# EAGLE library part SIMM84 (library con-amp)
AMP connector
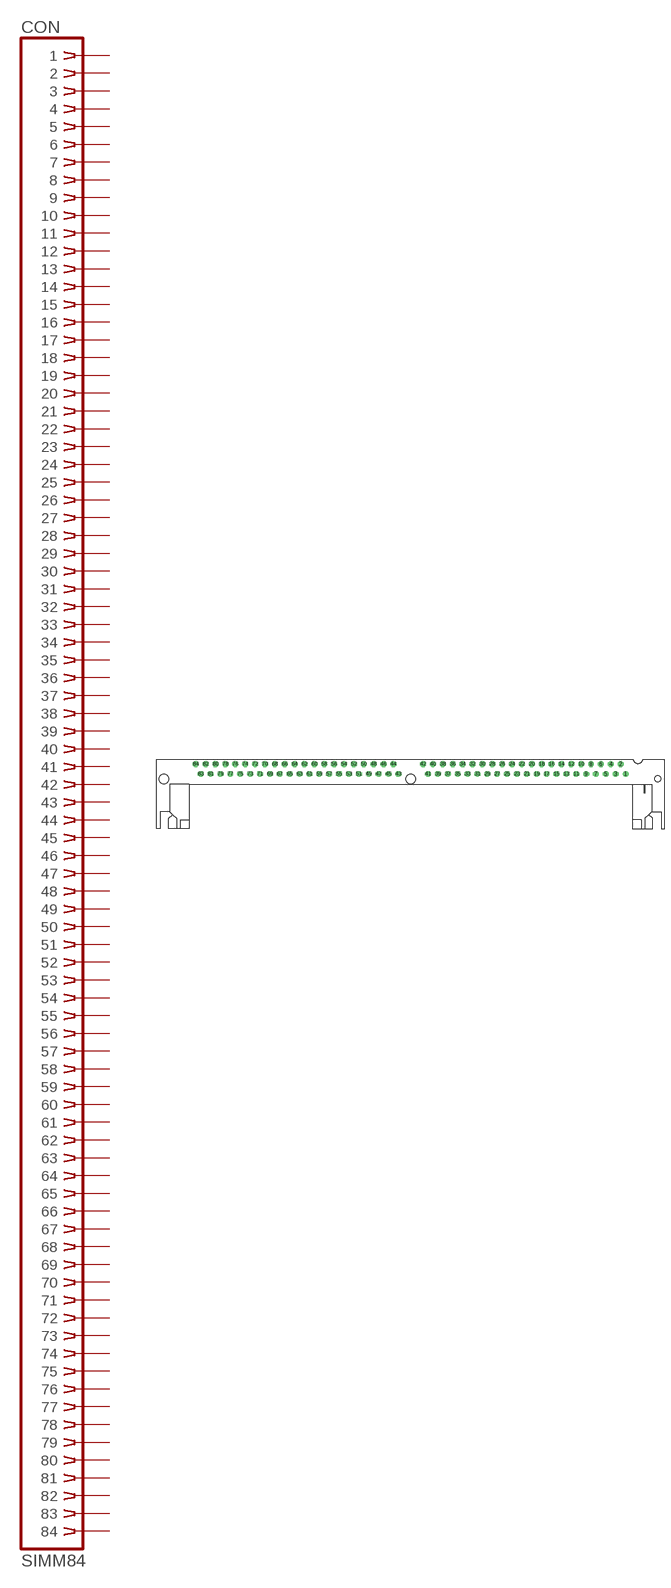
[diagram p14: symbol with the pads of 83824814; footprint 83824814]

Designator prefix CON

## SIMM84 (OC_FARNELL: unknown; OC_NEWARK: unknown)  [83824814]
1  1  pas
2  2  pas
3  3  pas
4  4  pas
5  5  pas
6  6  pas
7  7  pas
8  8  pas
9  9  pas
10  10  pas
11  11  pas
12  12  pas
13  13  pas
14  14  pas
15  15  pas
16  16  pas
17  17  pas
18  18  pas
19  19  pas
20  20  pas
21  21  pas
22  22  pas
23  23  pas
24  24  pas
25  25  pas
26  26  pas
27  27  pas
28  28  pas
29  29  pas
30  30  pas
31  31  pas
32  32  pas
33  33  pas
34  34  pas
35  35  pas
36  36  pas
37  37  pas
38  38  pas
39  39  pas
40  40  pas
41  41  pas
42  42  pas
43  43  pas
44  44  pas
45  45  pas
46  46  pas
47  47  pas
48  48  pas
49  49  pas
50  50  pas
51  51  pas
52  52  pas
53  53  pas
54  54  pas
55  55  pas
56  56  pas
57  57  pas
58  58  pas
59  59  pas
60  60  pas
61  61  pas
62  62  pas
63  63  pas
64  64  pas
65  65  pas
66  66  pas
67  67  pas
68  68  pas
69  69  pas
70  70  pas
71  71  pas
72  72  pas
73  73  pas
74  74  pas
75  75  pas
76  76  pas
77  77  pas
78  78  pas
79  79  pas
80  80  pas
81  81  pas
82  82  pas
83  83  pas
84  84  pas

## Footprint 83824814 (pad centres in mm)
SIMM II Socket
drill 1.016 round: 1 55.245,-1.27
drill 1.016 octagon: 2 53.975,1.27; 3 52.705,-1.27; 4 51.435,1.27; 5 50.165,-1.27; 6 48.895,1.27; 7 47.625,-1.27; 8 46.355,1.27; 9 45.085,-1.27; 10 43.815,1.27; 11 42.545,-1.27; 12 41.275,1.27; 13 40.005,-1.27; 14 38.735,1.27; 15 37.465,-1.27; 16 36.195,1.27; 17 34.925,-1.27; 18 33.655,1.27; 19 32.385,-1.27; 20 31.115,1.27; 21 29.845,-1.27; 22 28.575,1.27; 23 27.305,-1.27; 24 26.035,1.27; 25 24.765,-1.27; 26 23.495,1.27; 27 22.225,-1.27; 28 20.955,1.27; 29 19.685,-1.27; 30 18.415,1.27; 31 17.145,-1.27; 32 15.875,1.27; 33 14.605,-1.27; 34 13.335,1.27; 35 12.065,-1.27; 36 10.795,1.27; 37 9.525,-1.27; 38 8.255,1.27; 39 6.985,-1.27; 40 5.715,1.27; 41 4.445,-1.27; 42 3.175,1.27; 43 -3.175,-1.27; 44 -4.445,1.27; 45 -5.715,-1.27; 46 -6.985,1.27; 47 -8.255,-1.27; 48 -9.525,1.27; 49 -10.795,-1.27; 50 -12.065,1.27; 51 -13.335,-1.27; 52 -14.605,1.27; 53 -15.875,-1.27; 54 -17.145,1.27; 55 -18.415,-1.27; 56 -19.685,1.27; 57 -20.955,-1.27; 58 -22.225,1.27; 59 -23.495,-1.27; 60 -24.765,1.27; 61 -26.035,-1.27; 62 -27.305,1.27; 63 -28.575,-1.27; 64 -29.845,1.27; 65 -31.115,-1.27; 66 -32.385,1.27; 67 -33.655,-1.27; 68 -34.925,1.27; 69 -36.195,-1.27; 70 -37.465,1.27; 71 -38.735,-1.27; 72 -40.005,1.27; 73 -41.275,-1.27; 74 -42.545,1.27; 75 -43.815,-1.27; 76 -45.085,1.27; 77 -46.355,-1.27; 78 -47.625,1.27; 79 -48.895,-1.27; 80 -50.165,1.27; 81 -51.435,-1.27; 82 -52.705,1.27; 83 -53.975,-1.27; 84 -55.245,1.27
hole 2.438 at -63.5,-2.54
hole 1.575 at 63.5,-2.54
hole 2.438 at 0,-2.54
